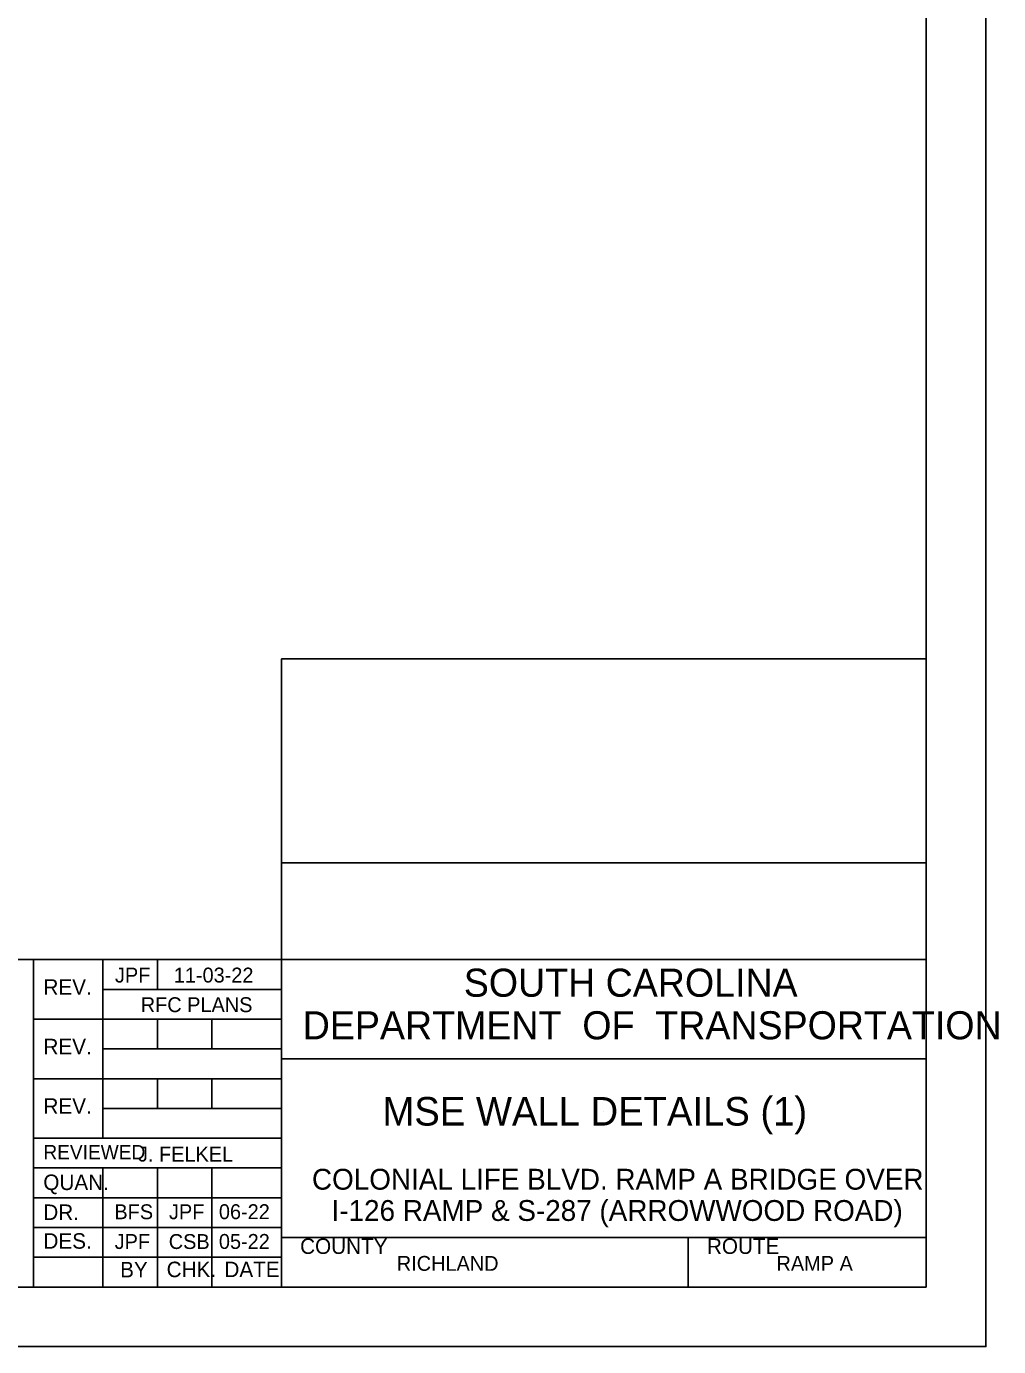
# Model space of a CAD drawing. Extents: x 96 to 240, y 601 to 689.
# Drawn here: x 207.6 to 240.27, y 601 to 645.36 of the extents above; entities that cross this region are included whole.
import ezdxf

# ---------------------------------------------------------------- set-up
doc = ezdxf.new("R2010")
doc.units = 0
for name, color, linetype in [('BR_BORDER LINES', 7, 'Continuous'), ('BR_TEXT', 7, 'Continuous'), ('Level 31', 7, 'Continuous')]:
    doc.layers.add(name, color=color, linetype=linetype)

msp = doc.modelspace()

# ---------------------------------------------------------------- linework, layer by layer
at = {"layer": 'BR_BORDER LINES'}
for p, q in [((237.837, 603.003), (237.837, 687.003)), ((216.17, 603.003), (216.17, 624.11)), ((216.17, 624.11), (237.837, 624.11)), ((216.17, 617.251), (237.837, 617.251)), ((186.375, 614.004), (207.836, 614.004)), ((207.836, 603.003), (207.836, 614.004)), ((207.836, 614.004), (237.837, 614.004)), ((210.169, 614.004), (210.169, 608.004)), ((212.003, 613.004), (212.003, 614.004)), ((210.169, 613.004), (216.17, 613.004)), ((207.836, 612.004), (216.17, 612.004)), ((212.003, 611.004), (212.003, 612.004)), ((213.836, 611.004), (213.836, 612.004)), ((210.169, 611.004), (216.17, 611.004)), ((216.17, 610.67), (216.17, 610.67)), ((216.17, 610.67), (237.838, 610.67)), ((207.836, 610.004), (216.17, 610.004)), ((212.003, 609.004), (212.003, 610.004)), ((213.836, 609.004), (213.836, 610.004)), ((210.169, 609.004), (216.17, 609.004)), ((207.836, 608.004), (216.17, 608.004)), ((207.836, 607.004), (216.17, 607.004)), ((210.169, 607.004), (210.169, 603.003)), ((212.003, 607.004), (212.003, 603.003)), ((213.836, 607.004), (213.836, 603.003)), ((207.836, 606.004), (216.17, 606.004)), ((207.836, 605.004), (216.17, 605.004)), ((216.17, 604.67), (237.837, 604.67)), ((216.56, 604.67), (237.837, 604.67)), ((229.837, 603.003), (229.837, 604.67)), ((207.836, 604.003), (216.17, 604.003)), ((103.173, 603.003), (237.837, 603.003))]:
    msp.add_line(p, q, dxfattribs=at)
at = {"layer": 'Level 31'}
msp.add_line((227.004, 608.909), (227.004, 608.909), dxfattribs=at)
msp.add_lwpolyline([(95.84, 689.004), (95.84, 601.004), (239.84, 601.004), (239.84, 689.004)], dxfattribs=at)

# ---------------------------------------------------------------- texts
at = {"layer": 'BR_TEXT'}
for s, height, p in [('JPF', 0.5, (210.578, 613.235)), ('11-03-22', 0.5, (212.554, 613.235)), ('SOUTH CAROLINA', 0.94348, (222.297, 612.757)), ('REV.', 0.52, (208.175, 612.825)), ('RFC PLANS', 0.5, (211.444, 612.24)), ('DEPARTMENT  OF  TRANSPORTATION', 0.94348, (216.886, 611.327)), ('REV.', 0.52, (208.175, 610.825)), ('MSE WALL DETAILS (1)', 0.96, (219.565, 608.429)), ('REV.', 0.52, (208.175, 608.825)), ('REVIEWED', 0.48, (208.172, 607.298)), ('J. FELKEL', 0.5, (211.352, 607.221)), ('QUAN.', 0.52, (208.17, 606.264)), ('COLONIAL LIFE BLVD. RAMP A BRIDGE OVER', 0.7, (217.196, 606.276)), ('I-126 RAMP & S-287 (ARROWWOOD ROAD)', 0.7, (217.854, 605.226)), ('DR.', 0.52, (208.17, 605.258)), ('BFS', 0.5, (210.558, 605.283)), ('JPF', 0.5, (212.393, 605.283)), ('06-22', 0.5, (214.069, 605.286)), ('DES.', 0.52, (208.175, 604.293)), ('JPF', 0.5, (210.568, 604.283)), ('CSB', 0.5, (212.384, 604.283)), ('05-22', 0.5, (214.069, 604.286)), ('COUNTY', 0.52, (216.798, 604.117)), ('ROUTE', 0.52, (230.466, 604.117)), ('BY', 0.52, (210.751, 603.331)), ('CHK.', 0.52, (212.314, 603.337)), ('DATE', 0.52, (214.255, 603.337)), ('RICHLAND', 0.5, (220.047, 603.549)), ('RAMP A', 0.5, (232.804, 603.549))]:
    msp.add_text(s, height=height, dxfattribs=at).set_placement(p)

doc.saveas('drawing.dxf')
